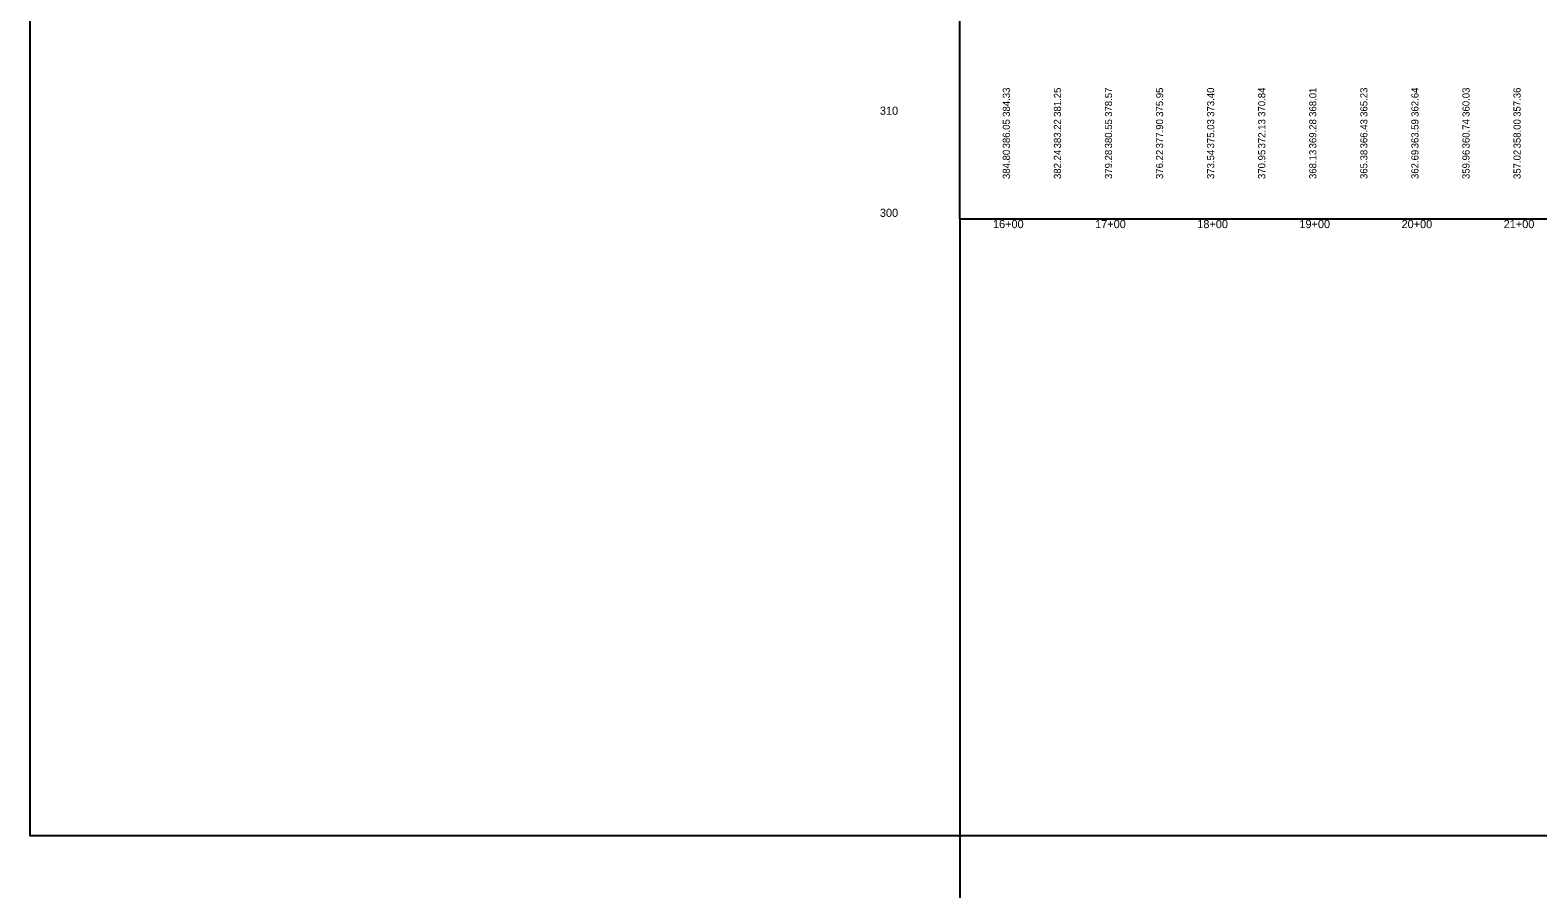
# Model space of a CAD drawing. Extents: x 2005261 to 2010661, y 1001568 to 1006764.
# Drawn here: x 2005261 to 2006738, y 1003412 to 1004253 of the extents above; entities that cross this region are included whole.
import ezdxf

# ---------------------------------------------------------------- set-up
doc = ezdxf.new("R2010")
doc.units = 0
for name, color, linetype in [('RD_DDB_ElevTX', 7, 'Continuous'), ('RD_DDB_StaTX', 7, 'Continuous'), ('RD_DDB_StripGrade', 7, 'Continuous'), ('RD_GPK_Profile_Cell', 7, 'Continuous'), ('RD_Sketch2', 7, 'Continuous'), ('RD_Sketch3', 7, 'Continuous'), ('RD_Sketch4', 7, 'Continuous')]:
    doc.layers.add(name, color=color, linetype=linetype)

msp = doc.modelspace()

# ---------------------------------------------------------------- linework, layer by layer
at = {"layer": 'RD_GPK_Profile_Cell'}
for q in [(2006171.7, 1006568.4), (2009471.7, 1004068.4), (2006171.7, 1001568.4)]:
    msp.add_line((2006171.7, 1004068.4), q, dxfattribs=at)
at = {"layer": 'RD_Sketch4'}
msp.add_lwpolyline([(2005261.5, 1006764.3), (2010661.5, 1006764.3), (2010661.5, 1003464.3), (2005261.5, 1003464.3)], close=True, dxfattribs=at)

# ---------------------------------------------------------------- texts
at = {"layer": 'RD_DDB_ElevTX'}
for s, p in [('310', (2006093.4, 1004170.4)), ('300', (2006093.4, 1004070.4))]:
    msp.add_text(s, height=8, dxfattribs=at).set_placement(p)
at = {"layer": 'RD_DDB_StaTX'}
for s, p in [('16+00', (2006204.1, 1004059.4)), ('17+00', (2006304.1, 1004059.4)), ('18+00', (2006404.1, 1004059.4)), ('19+00', (2006504.1, 1004059.4)), ('20+00', (2006604.1, 1004059.4)), ('21+00', (2006704.1, 1004059.4))]:
    msp.add_text(s, height=8, dxfattribs=at).set_placement(p)
at = {"layer": 'RD_DDB_StripGrade'}
for s, p in [('386.05', (2006220.7, 1004137.5)), ('383.22', (2006270.7, 1004137.5)), ('380.55', (2006320.7, 1004137.5)), ('377.90', (2006370.7, 1004137.5)), ('375.03', (2006420.7, 1004137.5)), ('372.13', (2006470.7, 1004137.5)), ('369.28', (2006520.7, 1004137.5)), ('366.43', (2006570.7, 1004137.5)), ('363.59', (2006620.7, 1004137.5)), ('360.74', (2006670.7, 1004137.5)), ('358.00', (2006720.7, 1004137.5))]:
    msp.add_text(s, height=7, rotation=90, dxfattribs=at).set_placement(p)
at = {"layer": 'RD_GPK_Profile_Cell'}
for s, p in [('153', (2006171.7, 1004068.5)), ('S53', (2006171.7, 1004068.5)), ('1550.000000', (2006171.7, 1004068.4)), ('300', (2006171.7, 1004068.4)), ('100', (2006171.7, 1004068.4)), ('10', (2006171.7, 1004068.4)), ('NOGAP', (2006171.7, 1004068.4))]:
    msp.add_text(s, height=0.00975, dxfattribs=at).set_placement(p)
at = {"layer": 'RD_Sketch2'}
for s, p in [('384.80', (2006220.7, 1004107.5)), ('382.24', (2006270.7, 1004107.5)), ('379.28', (2006320.7, 1004107.5)), ('376.22', (2006370.7, 1004107.5)), ('373.54', (2006420.7, 1004107.5)), ('370.95', (2006470.7, 1004107.5)), ('368.13', (2006520.7, 1004107.5)), ('365.38', (2006570.7, 1004107.5)), ('362.69', (2006620.7, 1004107.5)), ('359.96', (2006670.7, 1004107.5)), ('357.02', (2006720.7, 1004107.5))]:
    msp.add_text(s, height=7, rotation=90, dxfattribs=at).set_placement(p)
at = {"layer": 'RD_Sketch3'}
for s, p in [('384.33', (2006220.7, 1004168.4)), ('381.25', (2006270.7, 1004168.4)), ('378.57', (2006320.7, 1004168.4)), ('375.95', (2006370.7, 1004168.4)), ('373.40', (2006420.7, 1004168.4)), ('370.84', (2006470.7, 1004168.4)), ('368.01', (2006520.7, 1004168.4)), ('365.23', (2006570.7, 1004168.4)), ('362.64', (2006620.7, 1004168.4)), ('360.03', (2006670.7, 1004168.4)), ('357.36', (2006720.7, 1004168.4))]:
    msp.add_text(s, height=7, rotation=90, dxfattribs=at).set_placement(p)

doc.saveas('drawing.dxf')
